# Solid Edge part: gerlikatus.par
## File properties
Author: priit
Template: Normal.par
Last saved by: Anon
Revision: 6
Application: Solid Edge
Accuracy: 0,990
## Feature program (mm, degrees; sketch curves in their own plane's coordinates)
sketch for "unnamed Protrusion 1" plane through (0, 0, 0) normal (0, 0, 1) x-axis (1, 0, 0)
  line (3.2781, -28.3708) -> (3.2781, 21.6292)
  line (3.2781, 21.6292) -> (-38.5819, 21.6292)
  line (-38.5819, 21.6292) -> (-38.5819, -28.3708)
  line (-38.5819, -28.3708) -> (3.2781, -28.3708)
extrude "unnamed Protrusion 1" add finite 2 along +normal
sketch for "ExtrudedProtrusion_2" plane through (-17.6519, -3.3708, 2) normal (0, 0, 1) x-axis (1, 0, 0)
  line (-18.6089, 19.2754) -> (18.3911, 19.2754)
  line (18.3911, 19.2754) -> (18.3911, 21.7754)
  line (18.3911, 21.7754) -> (-18.6089, 21.7754)
  line (-18.6089, 21.7754) -> (-18.6089, 19.2754)
extrude "ExtrudedProtrusion_2" add finite 20 along +normal
swept protrusion "unnamed SweptProtrusion 1"
replace surface "unnamed ReplaceSurface 1"
chamfer "Chamfer_1" setback 0.5
swept protrusion "unnamed SweptProtrusion 2"
swept protrusion "unnamed SweptProtrusion 3"
sketch for "ExtrudedCutout_1" #1 plane through (0, 0, 0) normal (0, 0, 1) x-axis (1, 0, 0)
  line (-25.9551, -28.3708) -> (-38.5819, -13.4452)
  line (-38.5819, -13.4452) -> (-38.5819, -28.3708)
  line (-38.5819, -28.3708) -> (-25.9551, -28.3708)
sketch for "ExtrudedCutout_1" #2 plane through (0, 0, 0) normal (0, 0, 1) x-axis (1, 0, 0)
  line (3.2781, -13.4452) -> (-9.8208, -28.3708)
  line (-9.8208, -28.3708) -> (3.2781, -28.3708)
  line (3.2781, -28.3708) -> (3.2781, -13.4452)
extrude "ExtrudedCutout_1" cut finite 23.4819 along +normal
chamfer "unnamed Chamfer 1"
sketch for "unnamed Protrusion 2" #1 plane through (0, -13.3536, 0) normal (0, -1, 0) x-axis (1, 0, 0)
  circle centre (-34.2324, 1.0999) radius 0.9443
sketch for "unnamed Protrusion 2" #2 plane through (0, -13.3536, 0) normal (0, -1, 0) x-axis (1, 0, 0)
  circle centre (-2.2187, 1.0626) radius 0.945
extrude "unnamed Protrusion 2" add to key point along +normal
Other named dimensions: "ExtrudedSurface_5": FiniteDepth = 69.6403 mm | "ExtrudedSurface_6": FiniteDepth = 87.3843 mm | "ExtrudedSurface_7": FiniteDepth = 39.4491 mm
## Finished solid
Body 1: sheet body, 1 face, 4 edges, 4 vertices.
  Faces by surface: swept 1
  Edges by curve: line 2, spline 2
Body 2: sheet body, 1 face, 4 edges, 4 vertices.
  Faces by surface: swept 1
  Edges by curve: line 2, spline 2
Body 3: sheet body, 1 face, 4 edges, 4 vertices.
  Faces by surface: swept 1
  Edges by curve: line 2, spline 2
Body 4: solid body, 31 faces, 76 edges, 43 vertices.
  Faces by surface: plane 25, spline 3, cylinder 2, swept 1
  Edges by curve: line 51, intersection 12, circle 7, ellipse 6
Bounding box of the edges (mm; curved faces can reach further): 87.384 x 67.820 x 69.640, from (-61.2172, -28.3708, -32.8201) to (26.1671, 39.4491, 36.8201).
Cylindrical faces by radius (mm): R0.9443 x1, R0.945 x1
Planar faces by outward normal: +x 2, +y 4, +z 1, -x 2, -y 4, -z 1, oblique 11
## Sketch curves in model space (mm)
circle centre (-2.2187, -13.3536, 1.0626) radius 0.945
circle centre (-34.2324, -13.3536, 1.0999) radius 0.9443
line (-9.8208, -28.3708, 0) -> (3.2781, -28.3708, 0)
line (3.2781, -28.3708, 0) -> (3.2781, -13.4452, 0)
line (3.2781, -13.4452, 0) -> (-9.8208, -28.3708, 0)
line (-38.5819, -28.3708, 0) -> (-25.9551, -28.3708, 0)
line (-25.9551, -28.3708, 0) -> (-38.5819, -13.4452, 0)
line (-38.5819, -13.4452, 0) -> (-38.5819, -28.3708, 0)
circle centre (-17.7165, 15.9046, 20.6068) radius 1.3936
spline (-17.6519, -24.6222, 1.5) -> (-17.6519, -4.094, 20.0811) -> (-17.6519, 15.9046, 19.5409)
circle centre (-33.877, 0, 2) radius 1.3151
spline (-34.2324, 0, 1.0999) -> (-18.5936, 0, 20.6665) -> (-2.2187, 0, 1.0626)
spline (-38.0088, 0, 16.1279) -> (-17.8105, 0, 21.9993) -> (2.4276, 0, 16.687)
circle centre (-34.1047, 15.9046, 13.8014) radius 0.92
spline (-17.525, -25.36, 0) -> (-17.525, -6.4013, 10.5311) -> (-17.525, 15.8431, 13.8014)
spline (-34.1174, 15.9046, 2) -> (-17.7876, -24.0734, 2) -> (-1.9658, 16.7483, 2)
line (-36.2608, 15.9046, 2) -> (0.7392, 15.9046, 2)
line (0.7392, 15.9046, 2) -> (0.7392, 18.4046, 2)
line (0.7392, 18.4046, 2) -> (-36.2608, 18.4046, 2)
line (-36.2608, 18.4046, 2) -> (-36.2608, 15.9046, 2)
line (-38.5819, -28.3708, 0) -> (3.2781, -28.3708, 0)
line (3.2781, -28.3708, 0) -> (3.2781, 21.6292, 0)
line (3.2781, 21.6292, 0) -> (-38.5819, 21.6292, 0)
line (-38.5819, 21.6292, 0) -> (-38.5819, -28.3708, 0)
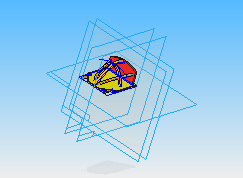
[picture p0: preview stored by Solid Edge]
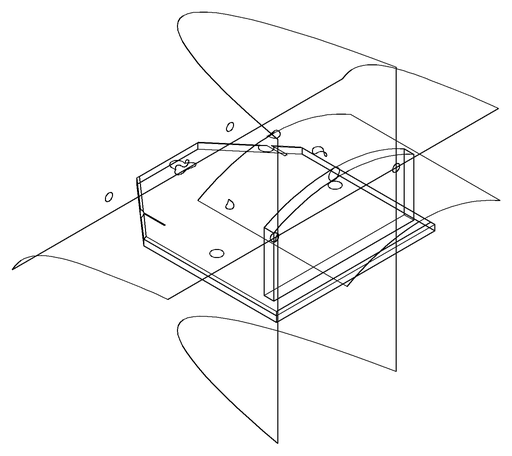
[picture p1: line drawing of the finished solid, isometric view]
